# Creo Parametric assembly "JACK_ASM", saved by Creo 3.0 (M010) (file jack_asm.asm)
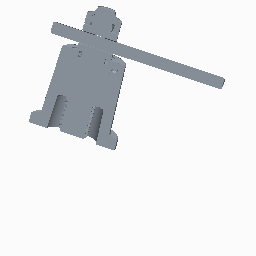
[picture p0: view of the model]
Units: millimeter Newton Second (mmNs); MM, TONNE, SECS

Created from: MMNS_ASM_DESIGN.ASM

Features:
  1. datum plane "ASM_RIGHT"
  2. datum plane "ASM_TOP"
  3. datum plane "ASM_FRONT"
  4. coordinate system
  5. component "JACK_1"
  6. component "JACK_2"
  7. component "JACK_4"
  8. component "JACK_3"
  9. component "JACK_5"
  10. component "JACK_6"
  11. component "JACK_7"

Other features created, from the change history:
  planar section "XSEC0001" (5 times)
  component "JACK_6.PRT"
  planar section "A"
  planar section "B"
